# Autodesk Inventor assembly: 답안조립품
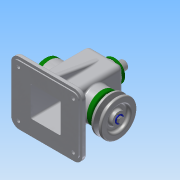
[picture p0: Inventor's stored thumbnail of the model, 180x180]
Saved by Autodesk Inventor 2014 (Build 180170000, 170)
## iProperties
Created: 2015-12
Part Number: 답안조립품
Document SubType Name: Assembly
Designer: Administrator
Author: Administrator
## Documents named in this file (19)
- D:\451225V1019\답안조립품.iam
- D:\451225V1019\본체.ipt
- D:\451225V1019\편심축.ipt
- D:\451225V1019\키 5 x 5 x 14.ipt
- D:\451225V1019\볼트 M6 x 12.ipt
- D:\451225V1019\와셔.ipt
- D:\451225V1019\V-벨트풀리.ipt
- D:\451225V1019\베어링 15 x 35 x 11.ipt
- D:\451225V1019\멈춤링 15 x 1.ipt
- D:\451225V1019\뒤커버.ipt
- D:\451225V1019\볼트 M4 x 10.ipt
- D:\451225V1019\앞커버.ipt
- D:\451225V1019\오일실 15 25 7.ipt
- D:\451225V1019\상부부시.ipt
- D:\451225V1019\슬라이드바.ipt
- D:\451225V1019\고정핀.ipt
- D:\451225V1019\링크.ipt
- D:\451225V1019\멈춤링 6 x 5.ipt
- D:\451225V1019\볼트 M3 x 8.ipt
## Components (15 placed, 5 different names)
1. ISO 4018 M6 x 12:1
2. V-벨트풀리:1
3. 고정핀:1
4. ISO 4762 M4 x 10:2
5. ISO 4762 M4 x 10:3
6. ISO 4762 M4 x 10:4
7. ISO 4762 M4 x 10:5
8. ISO 4762 M3 x 8:1
9. ISO 4762 M3 x 8:2
10. ISO 4762 M3 x 8:3
11. ISO 4762 M3 x 8:4
12. ISO 4762 M4 x 10:1
13. ISO 4762 M4 x 10:6
14. ISO 4762 M4 x 10:7
15. ISO 4762 M4 x 10:8
